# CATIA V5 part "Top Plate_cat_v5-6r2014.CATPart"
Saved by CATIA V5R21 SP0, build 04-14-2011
Part number: Top Plate
Bounding box of the stored display mesh (mm): x -125 to 125, y 0 to 150, z 180 to 210
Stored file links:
  D:\APS\CATIA V5-6R-2013-Project\CATIA V5-6R2013_partfiles\Tutorials\c12_catia_v5-6r2013_tut\c12tut2\Top Plate_cat_v5-6r2013.CATPart
  D:\APS\CATIA V5-6R-2013-Project\CATIA V5-6R2013_partfiles\Tutorials\c12_catia_v5-6r2013_tut\c12tut2\Assembly_cat_v5-6r2013.CATProduct
  D:\CATIA V5R21 E-RESOURCES\CATIA-V5R21\catia-v5r21-Tut\c12-catia-v5r21-tut\c12-catia-v5r21-tut02\Bush.CATPart
  D:\CATIA V5R21 E-RESOURCES\CATIA-V5R21\catia-v5r21-Tut\c12-catia-v5r21-tut\c12-catia-v5r21-tut02\Bottom Plate.CATPart
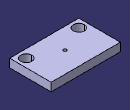
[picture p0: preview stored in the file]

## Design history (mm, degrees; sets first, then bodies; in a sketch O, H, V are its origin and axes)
Set1
  DatumSurface1: linked copy from another document
  DatumCurve1 to DatumCurve5: linked copy from another document
Body1 (main body)
  Sketch1 on face of DatumSurface1, origin (0, 0, 210), H (1, 0, 0), V (0, 1, 0)
    projected line E1 (-125, 0) -> (125, 0) from edge of DatumCurve1
    point P1 (-125, 0)
    point P2 (125, 0)
    projected line E2 (125, 0) -> (125, 150) from edge of DatumCurve2
    point P3 (125, 0)
    point P4 (125, 150)
    projected line E3 (125, 150) -> (-125, 150) from edge of DatumCurve3
    point P5 (125, 150)
    point P6 (-125, 150)
    projected line E4 (-125, 150) -> (-125, 0) from edge of DatumCurve4
    point P7 (-125, 150)
    point P8 (-125, 0)
    projected circle E5 centre (95, 30) radius 20 from edge of DatumCurve5
    circle A1 centre (-95, 30) radius 20
    symmetry: E5 A1 V
    coincidence: P1 P8, P2 P3, P4 P5, P6 P7
  Pad1: profile Sketch1, direction (0, 0, -1), length 30
  Sketch2 on face of Pad1, origin (0, 0, 210), H (1, 0, 0), V (0, 1, 0)
    circle A1 centre (0, 75) radius 6
    point P1 (0, 75)
    reference projected line E1 (-125, 0) -> (125, 0) from edge [face of Pad1 | face of Pad1]
    radius A1 = 6
    distance E1 P1 = 75
    coincidence: P1 V
  Pocket1: profile Sketch2, direction (0, 0, -1), through (limit type 6)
